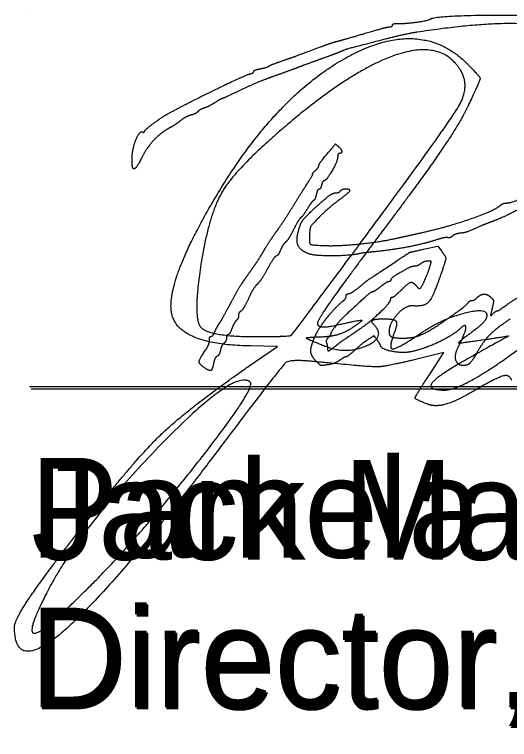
# Model space of a CAD drawing. Extents: x 0 to 81.5, y 0 to 35.2.
# Drawn here: x 24.504 to 25.199, y 6.933 to 7.951 of the extents above; entities that cross this region are included whole.
import ezdxf

# ---------------------------------------------------------------- set-up
doc = ezdxf.new("R2010")
doc.units = 0
doc.layers.add('SH_Data', color=7, linetype='Continuous')
doc.layers.add('SH_Text', color=7, linetype='Continuous')

msp = doc.modelspace()

# ---------------------------------------------------------------- linework, layer by layer
at = {"layer": 'SH_Data'}
for p, q in [((24.5257, 7.9507), (24.5257, 7.9507)), ((24.5257, 7.4285), (28.0257, 7.4285)), ((24.5279, 7.4256), (28.0279, 7.4256)), ((24.5279, 7.4256), (28.0279, 7.4256))]:
    msp.add_line(p, q, dxfattribs=at)
at = {"layer": 'SH_Text'}
msp.add_line((24.9902, 7.6306), (24.9902, 7.6306), dxfattribs=at)
for points in [[(25.0802, 7.6218), (25.0982, 7.6258), (25.1028, 7.6196)], [(24.8425, 7.4637), (24.8732, 7.4849), (24.8354, 7.4856)], [(25.0855, 7.4438), (25.1067, 7.4762), (25.0649, 7.4661)]]:
    msp.add_lwpolyline(points, dxfattribs=at)
for points in [[(25.0876, 7.9443), (25.0944, 7.9485), (25.2114, 7.9508), (25.2458, 7.9474)], [(25.0308, 7.9334), (25.0329, 7.9334), (25.0346, 7.9345), (25.0346, 7.9359)], [(25.0346, 7.9359), (25.0346, 7.9373), (25.0386, 7.9383), (25.0436, 7.9381)], [(25.0436, 7.9381), (25.0531, 7.9379), (25.0841, 7.9422), (25.0876, 7.9443)], [(25.3182, 7.9167), (25.2677, 7.9357), (25.1597, 7.9397), (25.0694, 7.9259)], [(24.9978, 7.9248), (25.0139, 7.9295), (25.0288, 7.9334), (25.0308, 7.9334)], [(25.0694, 7.9259), (25.0601, 7.9245), (25.0401, 7.9201), (25.025, 7.9162)], [(24.7789, 7.6814), (24.8651, 7.8318), (25.0732, 7.9478), (25.1389, 7.8821)], [(24.959, 7.9136), (24.9642, 7.915), (24.9817, 7.92), (24.9978, 7.9248)], [(25.025, 7.9162), (24.974, 7.903), (24.9697, 7.9018), (24.959, 7.8974)], [(24.8786, 7.8852), (24.8933, 7.8903), (24.8997, 7.8926), (24.935, 7.9058)], [(24.935, 7.9058), (24.9429, 7.9087), (24.9537, 7.9123), (24.959, 7.9136)], [(25.1299, 7.873), (25.104, 7.915), (24.9779, 7.8738), (24.8825, 7.7922)], [(24.959, 7.8974), (24.9563, 7.8963), (24.9461, 7.8925), (24.9362, 7.8889)], [(24.8606, 7.878), (24.8619, 7.879), (24.87, 7.8822), (24.8786, 7.8852)], [(24.9362, 7.8889), (24.9263, 7.8853), (24.9111, 7.8798), (24.9026, 7.8765)], [(24.8402, 7.8709), (24.8402, 7.872), (24.8442, 7.8736), (24.8492, 7.8746)], [(24.8492, 7.8746), (24.8541, 7.8755), (24.8592, 7.877), (24.8606, 7.878)], [(24.9026, 7.8765), (24.894, 7.8733), (24.8778, 7.8674), (24.8666, 7.8634)], [(25.1389, 7.8821), (25.1577, 7.8634), (25.1577, 7.8583), (25.1394, 7.8199)], [(24.7226, 7.813), (24.7528, 7.8293), (24.8264, 7.8649), (24.8348, 7.8674)], [(24.8348, 7.8674), (24.8377, 7.8682), (24.8402, 7.8698), (24.8402, 7.8709)], [(24.9902, 7.6306), (25.1115, 7.7941), (25.144, 7.8503), (25.1299, 7.873)], [(24.8666, 7.8634), (24.8553, 7.8594), (24.835, 7.8509), (24.8213, 7.8444)], [(24.8213, 7.8444), (24.8077, 7.8379), (24.7961, 7.8326), (24.7955, 7.8326)], [(24.7855, 7.827), (24.7806, 7.8239), (24.7739, 7.8205), (24.7707, 7.8194)], [(24.7955, 7.8326), (24.7949, 7.8326), (24.7904, 7.8301), (24.7855, 7.827)], [(24.7615, 7.8143), (24.7597, 7.8125), (24.7553, 7.8103), (24.7518, 7.8095)], [(24.7707, 7.8194), (24.7674, 7.8184), (24.7633, 7.8161), (24.7615, 7.8143)], [(25.1394, 7.8199), (25.1284, 7.7969), (25.0767, 7.7214), (25.0245, 7.652)], [(24.6866, 7.7864), (24.6866, 7.7885), (24.712, 7.8073), (24.7226, 7.813)], [(24.7518, 7.8095), (24.7483, 7.8086), (24.7416, 7.805), (24.737, 7.8014)], [(24.737, 7.8014), (24.7323, 7.7978), (24.7252, 7.7931), (24.7211, 7.791)], [(24.6694, 7.7485), (24.6695, 7.7617), (24.6801, 7.7883), (24.6843, 7.7857)], [(24.6843, 7.7857), (24.6855, 7.785), (24.6866, 7.7853), (24.6866, 7.7864)], [(24.7211, 7.791), (24.7107, 7.7857), (24.6908, 7.7649), (24.6845, 7.7527)], [(24.8825, 7.7922), (24.8159, 7.7352), (24.7771, 7.6711), (24.766, 7.5998)], [(24.9368, 7.7475), (24.9553, 7.7696), (24.9546, 7.769), (24.9587, 7.7656)], [(24.9587, 7.7656), (24.963, 7.7621), (24.9639, 7.7558), (24.9602, 7.7558)], [(25.1942, 7.6862), (25.2083, 7.6862), (25.2763, 7.7321), (25.3108, 7.7649)], [(24.6845, 7.7527), (24.6779, 7.7398), (24.6726, 7.733), (24.6708, 7.7348)], [(24.9602, 7.7558), (24.9588, 7.7558), (24.9578, 7.7535), (24.9578, 7.7507)], [(24.6708, 7.7348), (24.67, 7.7356), (24.6693, 7.7418), (24.6694, 7.7485)], [(24.9314, 7.7388), (24.9314, 7.74), (24.9338, 7.7439), (24.9368, 7.7475)], [(24.9578, 7.7507), (24.9578, 7.7452), (24.9418, 7.7174), (24.9387, 7.7174)], [(24.9266, 7.7318), (24.9292, 7.7345), (24.9314, 7.7376), (24.9314, 7.7388)], [(24.9138, 7.7113), (24.9194, 7.72), (24.9234, 7.727), (24.9228, 7.727)], [(24.9228, 7.727), (24.9222, 7.727), (24.9239, 7.7292), (24.9266, 7.7318)], [(24.9387, 7.7174), (24.9376, 7.7174), (24.936, 7.7147), (24.9352, 7.7114)], [(24.8918, 7.6763), (24.8984, 7.687), (24.9083, 7.7027), (24.9138, 7.7113)], [(24.9315, 7.7054), (24.9303, 7.7054), (24.9286, 7.7022), (24.9278, 7.6982)], [(24.9352, 7.7114), (24.9344, 7.7081), (24.9327, 7.7054), (24.9315, 7.7054)], [(24.9554, 7.7006), (24.9579, 7.7006), (24.9606, 7.7017), (24.9614, 7.703)], [(24.9746, 7.7034), (24.9746, 7.7023), (24.9678, 7.6964), (24.9596, 7.6903)], [(24.9614, 7.703), (24.9632, 7.7059), (24.9746, 7.7062), (24.9746, 7.7034)], [(24.923, 7.6765), (24.9386, 7.6911), (24.9514, 7.7006), (24.9554, 7.7006)], [(24.9278, 7.6982), (24.9269, 7.6943), (24.9252, 7.6904), (24.9239, 7.6896)], [(25.2483, 7.6978), (25.2291, 7.686), (25.1879, 7.665), (25.1738, 7.6599)], [(24.8354, 7.4856), (24.7375, 7.4873), (24.7141, 7.5684), (24.7789, 7.6814)], [(24.9239, 7.6896), (24.9226, 7.6889), (24.9188, 7.6837), (24.9154, 7.6782)], [(24.9596, 7.6903), (24.9513, 7.6842), (24.9388, 7.6733), (24.9318, 7.6661)], [(25.0742, 7.6443), (25.1111, 7.6525), (25.1774, 7.6754), (25.186, 7.6829)], [(25.186, 7.6829), (25.188, 7.6847), (25.1917, 7.6862), (25.1942, 7.6862)], [(24.87, 7.6434), (24.8754, 7.6509), (24.8852, 7.6657), (24.8918, 7.6763)], [(24.9016, 7.6418), (24.9044, 7.6549), (24.9105, 7.6649), (24.923, 7.6765)], [(24.9154, 7.6782), (24.912, 7.6727), (24.9079, 7.6671), (24.9062, 7.6658)], [(24.9062, 7.6658), (24.9046, 7.6644), (24.8999, 7.6568), (24.8959, 7.6488)], [(24.9318, 7.6661), (24.9211, 7.6552), (24.9189, 7.6515), (24.9184, 7.6433)], [(25.0245, 7.652), (24.9722, 7.5826), (24.9295, 7.522), (24.9295, 7.5172)], [(25.1581, 7.6537), (25.1411, 7.6462), (25.1362, 7.6445), (25.1296, 7.6438)], [(25.1738, 7.6599), (25.1691, 7.6582), (25.1621, 7.6554), (25.1581, 7.6537)], [(24.8533, 7.6178), (24.8571, 7.6244), (24.8647, 7.6359), (24.87, 7.6434)], [(24.8959, 7.6488), (24.8919, 7.6409), (24.8868, 7.6329), (24.8846, 7.6311)], [(24.917, 7.615), (24.9065, 7.6189), (24.8994, 7.6313), (24.9016, 7.6418)], [(24.9184, 7.6433), (24.9175, 7.6298), (24.9216, 7.627), (24.9422, 7.6264)], [(25.0406, 7.6368), (25.0485, 7.6386), (25.0636, 7.6419), (25.0742, 7.6443)], [(25.1296, 7.6438), (25.1257, 7.6434), (25.1208, 7.6415), (25.1188, 7.6397)], [(24.844, 7.4987), (24.8907, 7.4987), (24.8953, 7.5028), (24.9902, 7.6306)], [(24.8846, 7.6311), (24.8825, 7.6293), (24.8792, 7.6242), (24.8774, 7.6198)], [(24.9422, 7.6264), (24.9614, 7.6259), (25.0193, 7.632), (25.0406, 7.6368)], [(25.094, 7.6338), (25.0775, 7.6285), (25.0324, 7.62), (25.0086, 7.6177)], [(25.112, 7.6375), (25.1103, 7.6381), (25.1022, 7.6365), (25.094, 7.6338)], [(25.1188, 7.6397), (25.1167, 7.6379), (25.1136, 7.6369), (25.112, 7.6375)], [(25.0262, 7.5954), (25.0578, 7.6164), (25.0592, 7.6171), (25.0802, 7.6218)], [(24.8402, 7.5972), (24.8436, 7.6019), (24.8495, 7.6112), (24.8533, 7.6178)], [(24.8717, 7.6118), (24.8704, 7.6118), (24.8649, 7.6039), (24.8596, 7.5943)], [(24.8774, 7.6198), (24.8755, 7.6154), (24.873, 7.6118), (24.8717, 7.6118)], [(24.9882, 7.6151), (24.9745, 7.6121), (24.925, 7.612), (24.917, 7.615)], [(25.0086, 7.6177), (25.0003, 7.6169), (24.9911, 7.6158), (24.9882, 7.6151)], [(25.1028, 7.6196), (25.1095, 7.6109), (25.1093, 7.606), (25.1016, 7.5835)], [(24.766, 7.5998), (24.7545, 7.5264), (24.776, 7.4987), (24.844, 7.4987)], [(25.0743, 7.6009), (25.0717, 7.599), (25.0678, 7.5974), (25.0656, 7.5974)], [(25.0842, 7.6045), (25.0813, 7.6045), (25.0769, 7.6029), (25.0743, 7.6009)], [(25.0875, 7.598), (25.0892, 7.6038), (25.0888, 7.6046), (25.0842, 7.6045)], [(25.1076, 7.4237), (25.1307, 7.4237), (25.2567, 7.5125), (25.369, 7.6079)], [(24.8267, 7.578), (24.8308, 7.5838), (24.8369, 7.5924), (24.8402, 7.5972)], [(24.8596, 7.5943), (24.8543, 7.5846), (24.8476, 7.5746), (24.8448, 7.5721)], [(24.9869, 7.5674), (25.0007, 7.5785), (24.9987, 7.5771), (25.0262, 7.5954)], [(25.0558, 7.5943), (25.0414, 7.5863), (25.0322, 7.58), (25.0322, 7.578)], [(25.0656, 7.5974), (25.0633, 7.5974), (25.059, 7.596), (25.0558, 7.5943)], [(25.0728, 7.5662), (25.0746, 7.5662), (25.0844, 7.5874), (25.0875, 7.598)], [(25.1016, 7.5835), (25.0913, 7.5536), (25.0793, 7.5405), (25.0634, 7.5419)], [(24.8078, 7.5458), (24.8141, 7.5577), (24.8226, 7.5722), (24.8267, 7.578)], [(24.8448, 7.5721), (24.8419, 7.5695), (24.8364, 7.5604), (24.8325, 7.5518)], [(25.0295, 7.5758), (25.0281, 7.5758), (25.0228, 7.5726), (25.0178, 7.5686)], [(25.0322, 7.578), (25.0322, 7.5768), (25.031, 7.5758), (25.0295, 7.5758)], [(25.0466, 7.5638), (25.0567, 7.5739), (25.0632, 7.5758), (25.0682, 7.5698)], [(25.0682, 7.5698), (25.0698, 7.5678), (25.0719, 7.5662), (25.0728, 7.5662)], [(24.9698, 7.5556), (24.9698, 7.5575), (24.9713, 7.559), (24.9731, 7.559)], [(25.0066, 7.5614), (25.0047, 7.5614), (24.9963, 7.5541), (24.971, 7.5309)], [(24.9731, 7.559), (24.975, 7.559), (24.9812, 7.5628), (24.9869, 7.5674)], [(25.0178, 7.5686), (25.0128, 7.5647), (25.0078, 7.5614), (25.0066, 7.5614)], [(25.0346, 7.5542), (25.0359, 7.5542), (25.0413, 7.5585), (25.0466, 7.5638)], [(25.1913, 7.5407), (25.2116, 7.5559), (25.2343, 7.5615), (25.2373, 7.5521)], [(24.8325, 7.5518), (24.8285, 7.5432), (24.8238, 7.5353), (24.8219, 7.5343)], [(24.9643, 7.5478), (24.9673, 7.5502), (24.9698, 7.5537), (24.9698, 7.5556)], [(24.9861, 7.5076), (25.0017, 7.518), (25.0322, 7.5468), (25.0322, 7.5511)], [(25.0322, 7.5511), (25.0322, 7.5528), (25.0332, 7.5542), (25.0346, 7.5542)], [(25.1409, 7.5463), (25.1419, 7.548), (25.1443, 7.5494), (25.1461, 7.5494)], [(25.1461, 7.5494), (25.1479, 7.5494), (25.1512, 7.5512), (25.1533, 7.5533)], [(25.1533, 7.5533), (25.1583, 7.5583), (25.1683, 7.5583), (25.1732, 7.5534)], [(25.1732, 7.5534), (25.1764, 7.5502), (25.1766, 7.5478), (25.1745, 7.5386)], [(24.7924, 7.5182), (24.7946, 7.5215), (24.8015, 7.5339), (24.8078, 7.5458)], [(24.9263, 7.4995), (24.9308, 7.51), (24.954, 7.5394), (24.9643, 7.5478)], [(25.0634, 7.5419), (25.053, 7.5427), (25.0298, 7.5174), (25.0298, 7.5051)], [(25.0982, 7.5145), (25.1168, 7.5269), (25.1392, 7.5436), (25.1409, 7.5463)], [(25.1745, 7.5386), (25.1722, 7.5284), (25.1723, 7.5279), (25.1761, 7.5313)], [(25.1819, 7.535), (25.1829, 7.535), (25.1871, 7.5376), (25.1913, 7.5407)], [(24.8219, 7.5343), (24.8201, 7.5332), (24.8186, 7.5303), (24.8186, 7.5278)], [(24.971, 7.5309), (24.9618, 7.5225), (24.9482, 7.5054), (24.9482, 7.5025)], [(25.0736, 7.5031), (25.1025, 7.5229), (25.167, 7.5404), (25.167, 7.5285)], [(25.167, 7.5285), (25.167, 7.5239), (25.1572, 7.5131), (25.1453, 7.5044)], [(25.1761, 7.5313), (25.1783, 7.5334), (25.1809, 7.535), (25.1819, 7.535)], [(24.7855, 7.5056), (24.7871, 7.5092), (24.7901, 7.5149), (24.7924, 7.5182)], [(24.8161, 7.5218), (24.8147, 7.5209), (24.8119, 7.516), (24.8098, 7.5108)], [(24.8186, 7.5278), (24.8186, 7.5253), (24.8174, 7.5226), (24.8161, 7.5218)], [(24.9638, 7.5165), (24.9894, 7.5224), (24.9934, 7.5212), (24.9795, 7.5118)], [(25.0086, 7.5155), (25.004, 7.52), (25.0103, 7.5237), (25.0225, 7.5237)], [(25.0225, 7.5237), (25.037, 7.5237), (25.0422, 7.5173), (25.0375, 7.505)], [(25.1998, 7.5235), (25.1801, 7.51), (25.1629, 7.493), (25.1545, 7.4786)], [(24.8098, 7.5108), (24.8077, 7.5056), (24.8051, 7.5014), (24.8039, 7.5014)], [(24.9295, 7.5172), (24.9295, 7.5124), (24.9449, 7.5121), (24.9638, 7.5165)], [(24.9795, 7.5118), (24.9692, 7.5048), (24.9495, 7.4987), (24.9357, 7.4981)], [(24.9399, 7.4855), (24.9698, 7.4735), (25.026, 7.498), (25.0086, 7.5155)], [(25.0497, 7.4966), (25.0628, 7.4966), (25.0818, 7.5037), (25.0982, 7.5145)], [(25.1301, 7.5104), (25.1206, 7.5012), (25.0818, 7.4824), (25.0634, 7.478)], [(25.1272, 7.4846), (25.1313, 7.4923), (25.1378, 7.5086), (25.1378, 7.5113)], [(25.1378, 7.5113), (25.1378, 7.5144), (25.1338, 7.5139), (25.1301, 7.5104)], [(24.7778, 7.4933), (24.7778, 7.4965), (24.7789, 7.499), (24.7802, 7.499)], [(24.7802, 7.499), (24.7816, 7.499), (24.7839, 7.502), (24.7855, 7.5056)], [(24.8039, 7.5014), (24.8027, 7.5014), (24.8018, 7.4994), (24.8018, 7.4969)], [(24.9357, 7.4981), (24.9133, 7.4972), (24.9138, 7.4959), (24.9399, 7.4855)], [(24.9279, 7.4638), (24.9203, 7.4714), (24.9197, 7.4843), (24.9263, 7.4995)], [(24.9482, 7.5025), (24.9482, 7.5017), (24.9465, 7.4994), (24.9444, 7.4973)], [(24.9546, 7.4853), (24.9621, 7.4914), (24.9674, 7.4951), (24.9861, 7.5076)], [(25.0132, 7.4941), (25.0087, 7.4999), (25.0086, 7.4999), (25.0019, 7.4954)], [(25.0298, 7.5051), (25.0298, 7.4999), (25.0376, 7.4966), (25.0497, 7.4966)], [(25.0375, 7.505), (25.0285, 7.4817), (25.0414, 7.4811), (25.0736, 7.5031)], [(25.1453, 7.5044), (25.1264, 7.4906), (25.1284, 7.4893), (25.161, 7.4942)], [(25.161, 7.4942), (25.1977, 7.4998), (25.1976, 7.4995), (25.1522, 7.4744)], [(24.772, 7.4791), (24.7752, 7.4838), (24.7778, 7.4902), (24.7778, 7.4933)], [(24.7983, 7.4895), (24.7964, 7.488), (24.7942, 7.4834), (24.7933, 7.4795)], [(24.8018, 7.4969), (24.8018, 7.4944), (24.8002, 7.4911), (24.7983, 7.4895)], [(24.9444, 7.4973), (24.9424, 7.4953), (24.9413, 7.492), (24.942, 7.4901)], [(24.942, 7.4901), (24.9428, 7.4882), (24.9434, 7.4851), (24.9434, 7.4832)], [(25.0019, 7.4954), (24.9937, 7.4901), (24.9911, 7.488), (24.9799, 7.478)], [(25.0177, 7.4867), (25.0177, 7.4875), (25.0156, 7.4908), (25.0132, 7.4941)], [(24.7703, 7.4554), (24.7633, 7.4603), (24.7637, 7.467), (24.772, 7.4791)], [(24.7933, 7.4795), (24.7924, 7.4755), (24.7903, 7.4717), (24.7886, 7.4711)], [(24.9434, 7.4832), (24.9434, 7.4784), (24.9468, 7.479), (24.9546, 7.4853)], [(24.9799, 7.478), (24.9751, 7.4737), (24.9703, 7.4702), (24.9692, 7.4702)], [(25.0634, 7.478), (25.0505, 7.4749), (25.0179, 7.4811), (25.0177, 7.4867)], [(25.1339, 7.4582), (25.1255, 7.4582), (25.1215, 7.474), (25.1272, 7.4846)], [(25.1545, 7.4786), (25.1464, 7.4645), (25.14, 7.4582), (25.1339, 7.4582)], [(24.7886, 7.4711), (24.7869, 7.4704), (24.7848, 7.4663), (24.7839, 7.4619)], [(24.9692, 7.4702), (24.9681, 7.4702), (24.9642, 7.4681), (24.9607, 7.4655)], [(25.1522, 7.4744), (25.1011, 7.4462), (25.0814, 7.4237), (25.1076, 7.4237)], [(24.5916, 7.2215), (24.6692, 7.322), (24.7493, 7.3993), (24.8425, 7.4637)], [(24.7839, 7.4619), (24.7821, 7.4521), (24.7779, 7.4501), (24.7703, 7.4554)], [(24.9237, 7.4638), (24.8903, 7.4671), (24.8786, 7.4566), (24.8019, 7.355)], [(25.0649, 7.4661), (25.0246, 7.4564), (25.0023, 7.456), (24.9237, 7.4638)], [(24.9441, 7.4592), (24.9354, 7.4579), (24.9333, 7.4585), (24.9279, 7.4638)], [(24.9607, 7.4655), (24.9571, 7.4629), (24.9497, 7.4601), (24.9441, 7.4592)], [(24.8354, 7.4345), (24.8145, 7.4554), (24.596, 7.2297), (24.5497, 7.1394)], [(25.0843, 7.4038), (25.0661, 7.4108), (25.0662, 7.4144), (25.0855, 7.4438)], [(25.202, 7.4374), (25.1991, 7.446), (25.1799, 7.4408), (25.1508, 7.4236)], [(24.6198, 7.1581), (24.6874, 7.2272), (24.8431, 7.4268), (24.8354, 7.4345)], [(25.1508, 7.4236), (25.1252, 7.4085), (25.0953, 7.3996), (25.0843, 7.4038)], [(24.8019, 7.355), (24.6496, 7.1529), (24.5045, 7.0243), (24.5045, 7.0913)], [(24.5045, 7.0913), (24.5045, 7.1009), (24.5437, 7.1595), (24.5916, 7.2215)], [(24.5497, 7.1394), (24.5184, 7.0784), (24.55, 7.0869), (24.6198, 7.1581)]]:
    msp.add_open_spline(points, degree=2, dxfattribs=at)

# ---------------------------------------------------------------- texts
for s, p in [('Pamela Boratyn', (24.5257, 7.1885)), ('Jack Marchbanks, PhD', (24.5279, 7.1856)), ('Director, Department of Transportation', (24.5257, 6.9785)), ('Director, Department of Transportation', (24.5279, 6.9756))]:
    msp.add_text(s, height=0.14, dxfattribs=at).set_placement(p)

doc.saveas('drawing.dxf')
